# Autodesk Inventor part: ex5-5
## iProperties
Author: Administrator
Created: 2001-09
Part Number: ex5-5
Document SubType Name: Modeling
Designer: Administrator
Control State: 0
Master: False
Checked Out: False
PropertySet Name: Design Tracking Control
Length Units: 11272
Angle Units: 11279
Time Units: 11290
Mass Units: 11286
Shininess: 3
Angle Display Precision: 2
Document Length Units: 11272
Document Angle Units: 11286
Document Time Units: 11279
Document Mass Units: 11290
Document Length Units Precision: 3
Document Angle Units Precision: 2
Compacted: False
PropertySet Name: _Private Model Information
Density: 0.0
Volumn: 0.0
Area: 0.0
PropertySet Name: Model Information
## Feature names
1. Revolution1
2. Hole1
3. Shell1
4. Loft1
